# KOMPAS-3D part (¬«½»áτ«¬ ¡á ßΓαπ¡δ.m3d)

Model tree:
1. Эскиз:1
2. Операция выдавливания:1
     Расстояние 1 = 14
3. Эскиз:2
4. Операция выдавливания:2
     Расстояние 1 = 3
5. Скругление:1
     Радиус = 2
6. Эскиз:3
7. Операция выдавливания:3
     Расстояние 1 = 3
8. Эскиз:4
9. Вырезать элемент выдавливания:1
     Расстояние 1 = 10
10. Эскиз:5
11. Вырезать элемент выдавливания:2
     Расстояние 2 = 50; Расстояние 1 = 50
12. Эскиз:6
13. Вырезать элемент выдавливания:3
     Расстояние 2 = 50; Расстояние 1 = 50
14. Скругление:2
     Радиус = 2
15. Скругление:3
     Радиус = 2
16. Скругление:4
     Радиус = 2
17. Скругление:5
     Радиус = 2
18. Скругление:6
     Радиус = 1
19. Эскиз:7
20. Вырезать элемент выдавливания:4
     Расстояние 1 = 30
21. Скругление:7
     Радиус = 2
